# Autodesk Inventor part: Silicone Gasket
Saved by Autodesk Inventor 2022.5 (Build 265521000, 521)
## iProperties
Created: 2024-07
Part Number: Silicone Gasket
Material: Generic
Document SubType Name: Modeling
Designer: AdminForWorker
Density: 1 g/cm^3
Appearance: Default
Title: Silicone Gasket
Author: AdminForWorker
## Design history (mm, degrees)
feature "Silicone Gasket"
body "Solid1"
